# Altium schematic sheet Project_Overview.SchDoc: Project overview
size A4; Date: Not used; ApprovedBy: Not used; CheckedBy: Not used; Author: Not used; CompanyName: STMicroelectronics; DrawnBy: Not used; Engineer: Not used; Organization: Not used; Address1: Not used; Address2: Not used; Address3: Not used; Address4: Not used; DocumentNumber: Not used; Revision: Not used; SheetNumber: 1; SheetTotal: 7
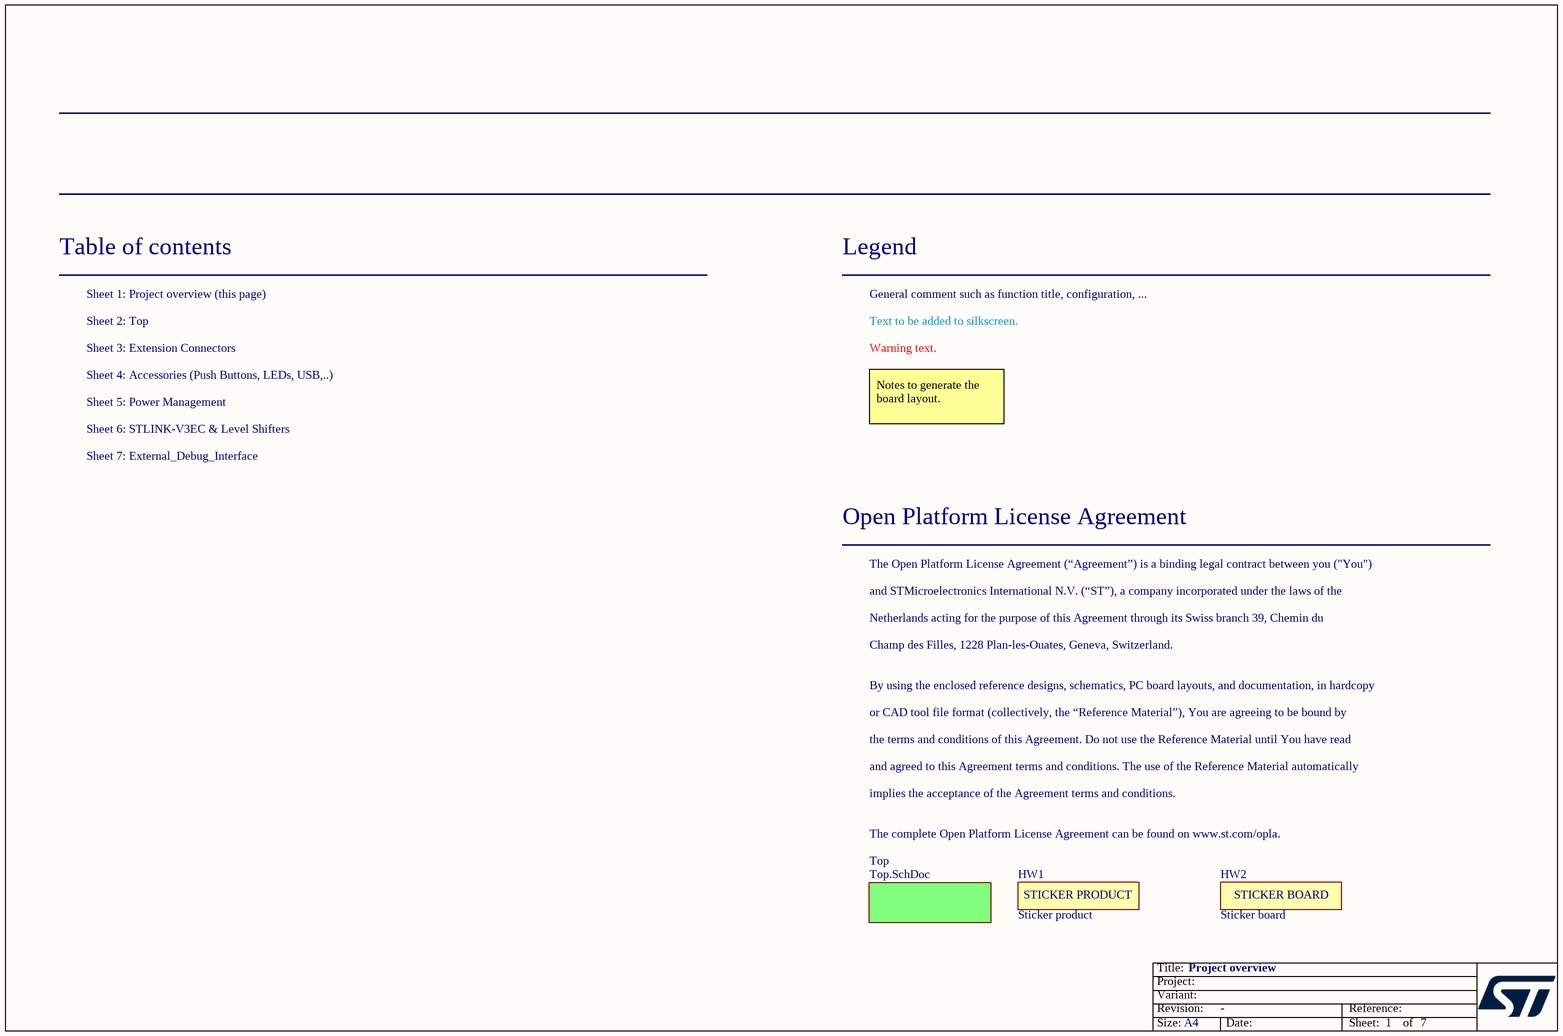
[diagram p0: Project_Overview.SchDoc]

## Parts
HW1  value Sticker product  [STICKER_PRODUCT_25X5]  (hidden comment: STICKER_PRODUCT)  (no BOM)
HW2  value Sticker board  [STICKER_BOARD_25X5]  (hidden comment: STICKER_BOARD)  (no BOM)

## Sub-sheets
Top = Top.SchDoc: no entries

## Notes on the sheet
- Table of contents
- Sheet 1: Project overview (this page)
- Legend
- General comment such as function title, configuration, ...
- Sheet 2: Top
- Sheet 3: Extension Connectors
- Sheet 4: Accessories (Push Buttons, LEDs, USB,..)
- Text to be added to silkscreen.
- Warning text.
- Sheet 6: STLINK-V3EC & Level Shifters
- Sheet 5: Power Management
- Notes to generate the board layout.
- Sheet 7: External_Debug_Interface
- Open Platform License Agreement
- The Open Platform License Agreement (“Agreement”) is a binding legal contract between you ("You")
- and STMicroelectronics International N.V. (“ST”), a company incorporated under the laws of the
- Netherlands acting for the purpose of this Agreement through its Swiss branch 39, Chemin du
- Champ des Filles, 1228 Plan-les-Ouates, Geneva, Switzerland.
- By using the enclosed reference designs, schematics, PC board layouts, and documentation, in hardcopy
- or CAD tool file format (collectively, the “Reference Material”), You are agreeing to be bound by
- the terms and conditions of this Agreement. Do not use the Reference Material until You have read
- and agreed to this Agreement terms and conditions. The use of the Reference Material automatically
- implies the acceptance of the Agreement terms and conditions.
- The complete Open Platform License Agreement can be found on www.st.com/opla.

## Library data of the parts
HW1 = MCD-02189: Sticker product 25x5 mm; Part_Type: Misc; Part_Preference: Recommended; Component_Country_Of_Origin: Unknown; ShowFields: YES; ID: 4289
HW2 = MCD-02190: Sticker board 25x5 mm; Part_Type: Misc; Part_Preference: Recommended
